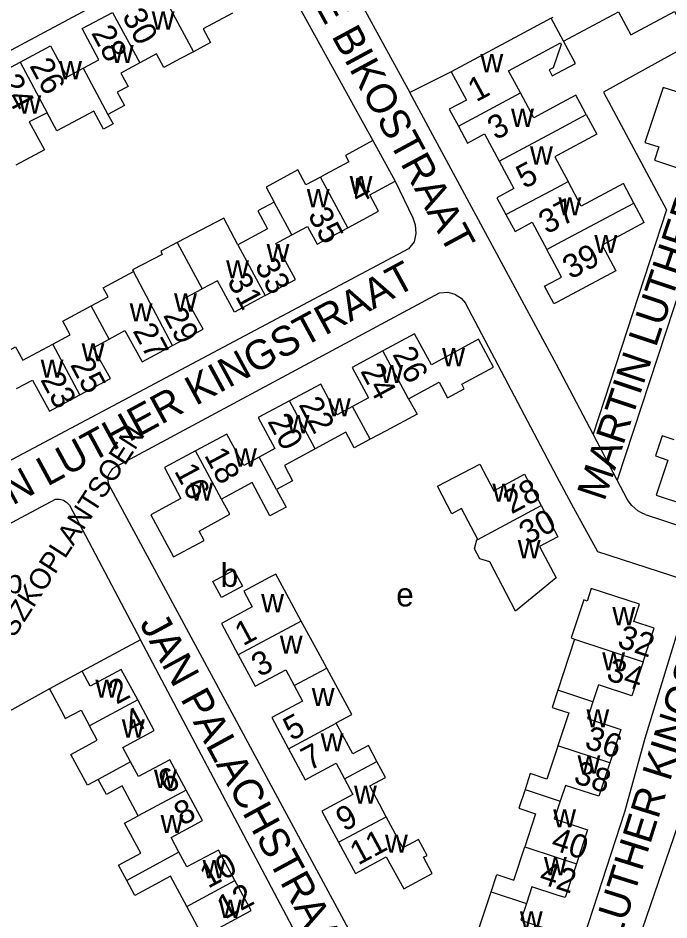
# Model space of a CAD drawing. Extents: x 157794 to 159375, y 380877 to 382306.
# Drawn here: x 159008.8 to 159118.9, y 381895.6 to 382048.3 of the extents above; entities that cross this region are included whole.
import ezdxf

# ---------------------------------------------------------------- set-up
doc = ezdxf.new("R2010")
doc.units = 0
for name, color, linetype in [('BLT_Basislijn', 7, 'Continuous'), ('BLT_Bebouwing', 7, 'Continuous'), ('BLT_Centroide', 7, 'Continuous'), ('BLT_Huisnummer', 7, 'Continuous'), ('BLT_Huisnummer_ tussenligend', 7, 'Continuous'), ('BLT_Onderverdeling_panden', 7, 'Continuous'), ('BLT_Straatnaam', 7, 'Continuous'), ('BLT_Straatnaam_verkleind', 7, 'Continuous')]:
    doc.layers.add(name, color=color, linetype=linetype)

msp = doc.modelspace()

# ---------------------------------------------------------------- linework, layer by layer
at = {"layer": 'BLT_Basislijn'}
for p, q in [((159055.96, 382050.89), (159068.83, 382027.6)), ((159136.42, 382050.21), (159110.16, 381970.11)), ((159128.85, 382047.44), (159107.86, 382035.78)), ((159082.09, 382039.22), (159075.06, 382035.72)), ((159099.88, 381989.68), (159075.06, 382035.72)), ((159107.86, 382035.78), (159118.53, 382015.87)), ((159072.56, 382020.7), (159075.55, 382014.49)), ((159118.53, 382015.87), (159106.07, 381977.89)), ((159106.07, 381977.89), (159099.88, 381989.68)), ((159110.16, 381970.11), (159106.07, 381977.89)), ((159102.85, 381965.36), (159100, 381970.63)), ((159111.87, 381966.86), (159110.16, 381970.11)), ((159114.9, 381964.3), (159117.82, 381963.35)), ((159117.82, 381963.35), (159132.79, 381958.4)), ((159029.46, 381943.09), (159019.61, 381937.75)), ((159131.04, 381942.86), (159105.03, 381866.63)), ((159014.08, 381934.75), (158994.51, 381923.94))]:
    msp.add_line(p, q, dxfattribs=at)
for points in [[(159056.72, 382069.29), (159075.06, 382035.72)], [(158949.21, 382011.67), (159048.45, 382064.86)], [(159125.52, 382036.72), (159121.03, 382038.16), (159120.28, 382035.82), (159117.94, 382036.57), (159114.86, 382027.26), (159117.18, 382026.53), (159116.46, 382024.26), (159120.86, 382022.82)], [(159075.55, 382014.49), (159075.98, 382013.3), (159076.07, 382011.86), (159075.82, 382010.47), (159074.85, 382009.29), (158980.01, 381958.86)], [(159024.73, 381972.06), (159080.11, 382001.82), (159081.48, 382001.93), (159082.7, 382001.61), (159083.75, 382000.93), (159084.49, 382000.08)], [(159100, 381970.63), (159084.49, 382000.08)], [(159024.73, 381972.06), (159024.29, 381971.41), (159023.98, 381970.76), (159023.95, 381970.05), (159024.07, 381969.44), (159071.25, 381881.93), (159072.69, 381879.52), (159076.12, 381876.12), (159077.49, 381875.32), (159092.19, 381870.11), (159095.54, 381870.21), (159096.74, 381870.93), (159098.02, 381872.52), (159100, 381878.71), (159111.44, 381913.93), (159114.91, 381926.43), (159120.96, 381946.35)], [(158985.3, 381950.95), (158986.46, 381951.58), (159015.1, 381966.91), (159015.78, 381966.9), (159016.44, 381966.71), (159017.03, 381966.33), (159017.48, 381965.88), (159029.46, 381943.09)], [(159114.9, 381964.3), (159114.27, 381964.58), (159113.68, 381964.93), (159113.13, 381965.34), (159112.64, 381965.82), (159112.2, 381966.35), (159111.87, 381966.86)], [(159121.35, 381953.31), (159106.87, 381957.97), (159102.85, 381965.36)], [(158994.07, 381923.44), (158982.1, 381906.19), (158981.46, 381904.6), (158981.34, 381899.92), (158982.25, 381897.5), (159026.42, 381815.66), (159028.37, 381813.47), (159029.25, 381813.04), (159032.7, 381813.07), (159049.22, 381822.15), (159051.23, 381824.01), (159053.32, 381826.75), (159067.69, 381869.91), (159066.93, 381871.95), (159061.42, 381882.67), (159029.46, 381943.09)]]:
    msp.add_lwpolyline(points, dxfattribs=at)
at = {"layer": 'BLT_Bebouwing'}
for p, q in [((159099.01, 382048.3), (159082.09, 382039.22)), ((159099.27, 382048.44), (159099.01, 382048.3)), ((159104.92, 382031.98), (159103.88, 382033.91)), ((159068.83, 382027.6), (159072.56, 382020.7)), ((159114.72, 382013.73), (159112.96, 382017.02)), ((159019.61, 381937.75), (159014.08, 381934.75))]:
    msp.add_line(p, q, dxfattribs=at)
for points in [[(159101.09, 382044.41), (159110.37, 382049.38), (159112.46, 382045.52), (159119.87, 382049.46), (159120.46, 382048.34), (159123.35, 382049.89), (159120.38, 382055.5), (159117.67, 382054), (159115.84, 382057.33)], [(159019.77, 382039.83), (159022.46, 382041.27), (159019.63, 382046.54), (159024.77, 382049.29)], [(159045.05, 382049.17), (159040.08, 382046.5), (159041.32, 382044.19), (159038.43, 382042.64)], [(159093.77, 382035.68), (159091.77, 382039.41), (159100.54, 382044.11), (159100.68, 382043.83), (159099.35, 382039.91), (159098.63, 382039.55), (159099.17, 382038.54), (159100, 382038.98), (159103.11, 382040.65), (159101.09, 382044.41)], [(159009.1, 382040.87), (159014.26, 382043.63), (159017.08, 382038.38), (159019.77, 382039.83)], [(159038.43, 382042.64), (159036.23, 382041.46), (159033.46, 382039.97), (159032.22, 382042.27), (159029.35, 382040.73)], [(159004.04, 382031.44), (159006.75, 382032.89), (159003.94, 382038.12), (159009.1, 382040.87)], [(159029.35, 382040.73), (159026.17, 382039.02), (159027.39, 382036.76), (159025.56, 382035.77), (159026.77, 382033.52), (159023.97, 382032.01)], [(159082.09, 382039.22), (159084.66, 382034.43), (159081.74, 382032.9), (159083.28, 382030.04)], [(159103.88, 382033.91), (159103.15, 382035.28), (159100, 382033.59), (159096.05, 382031.46), (159093.77, 382035.68)], [(159013.68, 382032.3), (159010.67, 382030.74), (159013.22, 382026), (159008.38, 382023.4)], [(159023.97, 382032.01), (159024.87, 382030.4), (159023.22, 382029.51), (159021.59, 382032.55), (159015.33, 382029.26), (159013.68, 382032.3)], [(159104.92, 382031.98), (159106.69, 382028.67), (159100, 382025.07), (159099.59, 382024.85), (159100, 382024.09), (159101.84, 382020.64)], [(159083.28, 382030.04), (159084.82, 382027.18), (159087.73, 382028.73), (159090.21, 382024.1)], [(159068.83, 382027.6), (159064.17, 382025.07), (159064.75, 382023.99), (159060.76, 382021.85), (159059.97, 382021.42)], [(159090.21, 382024.1), (159092.69, 382019.48), (159089.81, 382017.92), (159091.34, 382015.06)], [(159059.97, 382021.42), (159057.47, 382020.08), (159056.12, 382022.61), (159050.76, 382019.73), (159052.09, 382017.19)], [(159064.58, 382012.83), (159069.78, 382015.62), (159068.3, 382018.38), (159072.56, 382020.7)], [(159112.96, 382017.02), (159111.21, 382020.31), (159104.06, 382016.51), (159101.84, 382020.64)], [(159052.09, 382017.19), (159049.35, 382015.72), (159051, 382012.65), (159045.96, 382009.95)], [(159045.96, 382009.95), (159043.58, 382014.44), (159035.68, 382010.32)], [(159091.34, 382015.06), (159092.88, 382012.2), (159095.78, 382013.77), (159098.24, 382009.17)], [(159055.08, 382011.63), (159057.76, 382013.07), (159059.39, 382010.04), (159064.58, 382012.83)], [(159114.72, 382013.73), (159107.61, 382009.86), (159109.93, 382005.54), (159100, 382000.23), (159099.57, 382000), (159099.42, 382000), (159097.86, 382002.95), (159100, 382004.09), (159100.74, 382004.49), (159100, 382005.87), (159098.24, 382009.17)], [(159050.59, 382001.34), (159055.69, 382004.08), (159052.41, 382010.19), (159055.08, 382011.63)], [(159035.68, 382010.32), (159032.9, 382008.87), (159033.18, 382008.33), (159028.14, 382005.69), (159028.29, 382005.41)], [(159021.16, 381999.6), (159024.01, 382001.13), (159023.18, 382002.67), (159028.29, 382005.41)], [(159050.59, 382001.34), (159048.09, 382000), (159045.37, 381998.54), (159044.59, 382000), (159042.5, 382003.87), (159039.9, 382002.47)], [(159034.92, 381992.92), (159040.08, 381995.69), (159037.69, 382000), (159037.16, 382001), (159039.9, 382002.47)], [(159014.63, 381993.13), (159017.59, 381994.72), (159016.36, 381997.02), (159021.16, 381999.6)], [(159024.18, 381993.97), (159026.86, 381995.42), (159029.76, 381990.15), (159034.92, 381992.92)], [(159074.85, 381983.89), (159080.03, 381986.68), (159081.46, 381984.02), (159084.28, 381985.54), (159083.85, 381986.36), (159089.23, 381989.25), (159086.7, 381993.96), (159078.71, 381989.64), (159075.88, 381994.86), (159070.51, 381991.99)], [(159005.53, 381991.16), (159008.33, 381992.67), (159009.55, 381990.4), (159014.63, 381993.13)], [(159019.24, 381984.54), (159024.4, 381987.3), (159021.5, 381992.53), (159024.18, 381993.97)], [(159070.51, 381991.99), (159065.28, 381989.19), (159068.06, 381984.02), (159065.39, 381982.59)], [(159008.52, 381985.6), (159011.2, 381987.04), (159014.09, 381981.77), (159019.24, 381984.54)], [(159065.39, 381982.59), (159062.77, 381981.18), (159059.98, 381986.37), (159054.68, 381983.53)], [(159054.68, 381983.53), (159049.41, 381980.71), (159052.24, 381975.44), (159049.56, 381974)], [(159074.85, 381983.89), (159076.33, 381981.3), (159071.09, 381978.48), (159068.38, 381977.03)], [(159049.56, 381974), (159046.95, 381972.6), (159044.11, 381977.89), (159038.79, 381975.06)], [(159068.38, 381977.03), (159065.67, 381975.57), (159064.26, 381978.2), (159059.04, 381975.4)], [(159119.83, 381976.93), (159117.75, 381977.61), (159116.64, 381974.2), (159118.72, 381973.51), (159116.77, 381967.56), (159125.86, 381964.57), (159127.65, 381969.93), (159137.31, 381966.74), (159138.62, 381970.71), (159128.97, 381973.9)], [(159038.79, 381975.06), (159033.54, 381972.27), (159036.34, 381967.01), (159031.23, 381964.25), (159035.06, 381957.11), (159040.25, 381959.9), (159039.4, 381961.47), (159044.61, 381964.35), (159043.17, 381966.89)], [(159059.04, 381975.4), (159053.83, 381972.6), (159055.23, 381969.99), (159052.5, 381968.52)], [(159086.55, 381960.06), (159083.82, 381965.28), (159082.18, 381964.42), (159079.74, 381969.1), (159086.89, 381972.83), (159089.26, 381968.3), (159094.47, 381971.09), (159097.29, 381965.81)], [(159052.5, 381968.52), (159054.16, 381965.53), (159051.39, 381964.04), (159048.36, 381969.68), (159043.17, 381966.89)], [(159097.29, 381965.81), (159100, 381960.74), (159100.12, 381960.51), (159100, 381960.45), (159097.02, 381958.88), (159099.86, 381953.56), (159092.97, 381947.92), (159092.17, 381949.44), (159088.6, 381956.27), (159086.89, 381956.76), (159085.99, 381958.48), (159086.41, 381959.98), (159086.55, 381960.06)], [(159056.65, 381946.24), (159053.86, 381951.47), (159052.39, 381954.21), (159051.38, 381953.67), (159046.97, 381951.31), (159048.4, 381948.65), (159043.17, 381945.83), (159046.02, 381940.51)], [(159114.55, 381939.36), (159116.43, 381945.07), (159112.97, 381946.2), (159113.92, 381949.1), (159105.76, 381951.78), (159105.06, 381949.64), (159104.49, 381949.83), (159102.37, 381943.38), (159102.94, 381943.19)], [(159061.01, 381938.29), (159059.57, 381941), (159056.65, 381946.24)], [(159102.94, 381943.19), (159101.07, 381937.46), (159100.11, 381934.56)], [(159046.02, 381940.51), (159048.88, 381935.2), (159054.09, 381937.99), (159055.5, 381935.34)], [(159114.55, 381939.36), (159112.63, 381933.57), (159106.98, 381935.43), (159106.05, 381932.6)], [(159029.01, 381932.9), (159026.23, 381938.06), (159020.98, 381935.23), (159019.61, 381937.75)], [(159062.61, 381928.97), (159062.6, 381929), (159065.23, 381930.41), (159061.01, 381938.29)], [(159014.08, 381934.75), (159016.45, 381930.35), (159016.76, 381929.75), (159019.42, 381931.18), (159020.86, 381928.5)], [(159055.5, 381935.34), (159056.92, 381932.7), (159051.71, 381929.91), (159054.53, 381924.64)], [(159100.11, 381934.56), (159100, 381934.22), (159099.15, 381931.62), (159100, 381931.34), (159101.97, 381930.69), (159100.13, 381925.13)], [(159027.81, 381922.39), (159026.48, 381924.87), (159031.8, 381927.73), (159029.01, 381932.9)], [(159106.05, 381932.6), (159105.11, 381929.77), (159110.77, 381927.9), (159108.9, 381922.24)], [(159022.34, 381919.45), (159020.49, 381918.48), (159017.71, 381923.66), (159022.17, 381926.06), (159020.86, 381928.5)], [(159069.5, 381922.47), (159068.05, 381925.16), (159065.4, 381923.75), (159062.61, 381928.97)], [(159054.53, 381924.64), (159057.36, 381919.38), (159062.6, 381922.18), (159064.02, 381919.53)], [(159100.13, 381925.13), (159100, 381924.73), (159098.27, 381919.49), (159095.44, 381920.42), (159094.56, 381917.74)], [(159037.22, 381917.62), (159034.46, 381922.77), (159029.15, 381919.91), (159027.81, 381922.39)], [(159071.07, 381913.13), (159068.29, 381918.33), (159070.95, 381919.75), (159069.5, 381922.47)], [(159108.9, 381922.24), (159107.03, 381916.58), (159101.4, 381918.43), (159100.51, 381915.77)], [(159029.09, 381913.25), (159026.36, 381918.33), (159023.71, 381916.9), (159022.34, 381919.45)], [(159064.02, 381919.53), (159065.43, 381916.89), (159060.19, 381914.08), (159063.02, 381908.81)], [(159094.56, 381917.74), (159093.52, 381914.58), (159096.36, 381913.64), (159094.51, 381908.01)], [(159036, 381907.12), (159034.66, 381909.62), (159039.99, 381912.48), (159037.22, 381917.62)], [(159100.51, 381915.77), (159100, 381914.22), (159099.51, 381912.75), (159100, 381912.59), (159105.15, 381910.88), (159103.26, 381905.15)], [(159027.15, 381902.35), (159025.78, 381904.91), (159029.54, 381906.93), (159026.8, 381912.04), (159029.09, 381913.25)], [(159063.02, 381908.81), (159065.86, 381903.53), (159071.09, 381906.33), (159074.05, 381900.9), (159078.85, 381903.53), (159077.4, 381906.26), (159077.99, 381906.57), (159076.54, 381909.28), (159073.89, 381907.86), (159071.07, 381913.13)], [(159045.46, 381902.33), (159042.68, 381907.48), (159037.35, 381904.62), (159036, 381907.12)], [(159088.83, 381900.4), (159089.79, 381903.33), (159092.65, 381902.39), (159094.51, 381908.01)], [(159103.26, 381905.15), (159101.37, 381899.42), (159100, 381899.87), (159095.73, 381901.28), (159094.79, 381898.43)], [(159037.32, 381897.95), (159034.58, 381903.05), (159031.95, 381901.63), (159028.53, 381899.79), (159027.15, 381902.35)], [(159044.22, 381891.93), (159042.9, 381894.39), (159048.2, 381897.24), (159045.46, 381902.33)], [(159088.87, 381890.93), (159086.03, 381891.92), (159088.83, 381900.4)], [(159038.81, 381888.92), (159037.45, 381891.46), (159040.05, 381892.86), (159037.32, 381897.95)], [(159094.79, 381898.43), (159093.86, 381895.6), (159099.51, 381893.73), (159097.63, 381888.04)]]:
    msp.add_lwpolyline(points, dxfattribs=at)
msp.add_lwpolyline([(159041.74, 381952.95), (159045.31, 381954.86), (159046.76, 381952.15), (159043.2, 381950.24)], close=True, dxfattribs=at)
at = {"layer": 'BLT_Onderverdeling_panden'}
for p, q in [((159034.19, 382050.55), (159038.43, 382042.64)), ((159024.77, 382049.29), (159029.35, 382040.73)), ((159101.09, 382044.41), (159099.01, 382048.3)), ((159009.1, 382040.87), (159013.68, 382032.3)), ((159019.77, 382039.83), (159023.97, 382032.01)), ((159083.28, 382030.04), (159093.77, 382035.68)), ((159064.58, 382012.83), (159059.97, 382021.42)), ((159055.08, 382011.63), (159052.09, 382017.19)), ((159035.68, 382010.32), (159039.9, 382002.47)), ((159045.96, 382009.95), (159050.59, 382001.34)), ((159034.92, 381992.92), (159028.29, 382005.41)), ((159024.18, 381993.97), (159021.16, 381999.6)), ((159019.24, 381984.54), (159014.63, 381993.13)), ((159074.85, 381983.89), (159070.51, 381991.99)), ((159059.04, 381975.4), (159054.68, 381983.53)), ((159068.38, 381977.03), (159065.39, 381982.59)), ((159043.17, 381966.89), (159038.79, 381975.06)), ((159052.5, 381968.52), (159049.56, 381974)), ((159086.55, 381960.06), (159097.29, 381965.81)), ((159056.65, 381946.24), (159046.02, 381940.51)), ((159102.94, 381943.19), (159114.55, 381939.36)), ((159055.5, 381935.34), (159061.01, 381938.29)), ((159106.05, 381932.6), (159100.11, 381934.56)), ((159029.01, 381932.9), (159020.86, 381928.5)), ((159054.53, 381924.64), (159062.61, 381928.97)), ((159108.9, 381922.24), (159100.13, 381925.13)), ((159027.81, 381922.39), (159022.34, 381919.45)), ((159064.02, 381919.53), (159069.5, 381922.47)), ((159094.56, 381917.74), (159100.51, 381915.77)), ((159037.22, 381917.62), (159029.09, 381913.25)), ((159063.02, 381908.81), (159071.07, 381913.13)), ((159036, 381907.12), (159027.15, 381902.35)), ((159037.32, 381897.95), (159045.46, 381902.33)), ((159088.83, 381900.4), (159094.79, 381898.43))]:
    msp.add_line(p, q, dxfattribs=at)
for points in [[(159090.21, 382024.1), (159100, 382029.34), (159104.92, 382031.98)], [(159091.34, 382015.06), (159100, 382019.65), (159101.84, 382020.64)], [(159098.24, 382009.17), (159100, 382010.11), (159112.96, 382017.02)], [(159094.51, 381908.01), (159100, 381906.23), (159103.26, 381905.15)]]:
    msp.add_lwpolyline(points, dxfattribs=at)

# ---------------------------------------------------------------- texts
at = {"layer": 'BLT_Centroide'}
for s, p in [('w', (159031.38, 382046.38)), ('w', (159024.48, 382040.72)), ('w', (159087.01, 382039.16)), ('w', (159015.71, 382037.97)), ('w', (159008.81, 382032.17)), ('w', (159092.2, 382029.91)), ('w', (159095.41, 382023.53)), ('w', (159064.88, 382018.53)), ('w', (159057.63, 382016.31)), ('w', (159100.21, 382014.91)), ('w', (159106.3, 382008.53)), ('w', (159050.83, 382007.02)), ('w', (159043.98, 382004.25)), ('w', (159035.17, 381998.64)), ('w', (159027.66, 381996.97)), ('w', (159019.52, 381990.22)), ('w', (159080.54, 381989.38)), ('w', (159012.59, 381987.44)), ('w', (159070.06, 381986.53)), ('w', (159061.2, 381980.88)), ('w', (159054.23, 381978.05)), ('w', (159045.32, 381972.41)), ('w', (159037.92, 381966.62)), ('w', (159089.04, 381966.44)), ('w', (159093.33, 381956.88)), ('b', (159043.05, 381952.04)), ('p', (159006.6, 381950.96)), ('e', (159072.76, 381948.72)), ('w', (159049.91, 381947.73)), ('w', (159109.35, 381945.53)), ('w', (159053.06, 381940.72)), ('w', (159107.62, 381937.88)), ('w', (159021.84, 381933.28)), ('w', (159058.47, 381931.84)), ('w', (159104.95, 381928.25)), ('w', (159026.33, 381926.52)), ('w', (159059.98, 381924.19)), ('w', (159103.45, 381920.44)), ('w', (159031.77, 381918)), ('w', (159065.62, 381915.31)), ('w', (159032.88, 381910.36)), ('w', (159099.33, 381911.3)), ('w', (159070.87, 381907.03)), ('w', (159040, 381902.72)), ('w', (159097.77, 381903.22)), ('w', (159042.75, 381896)), ('w', (159093.69, 381894.06))]:
    msp.add_text(s, height=4, dxfattribs=at).set_placement(p)
at = {"layer": 'BLT_Huisnummer'}
for s, rotation, p in [('26', 298.2475, (159010.63, 382040.27)), ('1', 28.2838, (159086.29, 382034.04)), ('5', 27.9562, (159094.44, 382019.36)), ('4', 28.2376, (159066.26, 382016.78)), ('35', 298.1914, (159057.72, 382015)), ('39', 28.1416, (159102.29, 382004.02)), ('29', 298.1914, (159033.24, 381998.03)), ('26', 298.2591, (159072.05, 381991.41)), ('25', 298.1914, (159017.51, 381989.64)), ('20', 298.2586, (159050.89, 381980.08)), ('16', 298.0493, (159035.13, 381971.66)), ('28', 28.1484, (159092.27, 381964.28)), ('30', 28.1621, (159094.94, 381959.08)), ('1', 28.2851, (159046.85, 381941.96)), ('32', 341.7416, (159109.99, 381941.91)), ('2', 28.2378, (159025.43, 381932.06)), ('5', 28.2851, (159055.04, 381925.89)), ('36', 341.7416, (159104.45, 381924.82)), ('6', 28.2378, (159033.85, 381916.9)), ('11', 28.2851, (159066.32, 381904.84)), ('40', 341.7416, (159098.76, 381907.68)), ('10', 28.2378, (159040.92, 381900.91))]:
    msp.add_text(s, height=4, rotation=rotation, dxfattribs=at).set_placement(p)
at = {"layer": 'BLT_Huisnummer_ tussenligend'}
for s, rotation, p in [('30', 298.2475, (159026.29, 382048.69)), ('28', 298.2475, (159021.08, 382045.82)), ('24', 298.2475, (159005.42, 382037.55)), ('3', 28.2838, (159089.6, 382027.59)), ('37', 28.036, (159098.24, 382011.67)), ('33', 298.1914, (159048.73, 382006.45)), ('31', 298.1914, (159044.06, 382003.86)), ('27', 298.1914, (159028.11, 381995.39)), ('24', 298.2586, (159066.62, 381988.57)), ('23', 298.1914, (159012.48, 381987.12)), ('22', 298.2586, (159056.18, 381982.9)), ('18', 298.0493, (159040.2, 381974.35)), ('3', 28.2851, (159049.65, 381936.69)), ('34', 341.7416, (159108.13, 381936.35)), ('4', 28.2378, (159028.12, 381927)), ('7', 28.2851, (159058.06, 381920.83)), ('38', 341.7416, (159102.61, 381918.92)), ('8', 28.2378, (159036.55, 381911.51)), ('9', 28.2851, (159063.96, 381910.55)), ('42', 341.7416, (159096.75, 381901.95)), ('12', 28.2378, (159043.8, 381895.69))]:
    msp.add_text(s, height=4, rotation=rotation, dxfattribs=at).set_placement(p)
at = {"layer": 'BLT_Straatnaam'}
for s, height, rotation, p in [('MAHATMA GANDHILAAN', 5, 28.0837, (158964.75, 382027.28)), ('STEVE BIKOSTRAAT', 5, 298.4051, (159050.43, 382066.23)), ('MARTIN LUTHER KINGSTRAAT', 4.9999, 71.5304, (159107.99, 381966.37)), ('MARTIN LUTHER KINGSTRAAT', 5, 28.5304, (158989.55, 381955.84)), ('MARTIN LUTHER KINGSTRAAT', 5, 72.5304, (159102.24, 381865.46)), ('JAN PALACHSTRAAT', 5, 298.5304, (159029.24, 381945.84))]:
    msp.add_text(s, height=height, rotation=rotation, dxfattribs=at).set_placement(p)
at = {"layer": 'BLT_Straatnaam_verkleind'}
msp.add_text('JERZY POPIELUSZKOPLANTSOEN', height=3.5, rotation=57.2579, dxfattribs=at).set_placement((158988.42, 381912.68))

doc.saveas('drawing.dxf')
